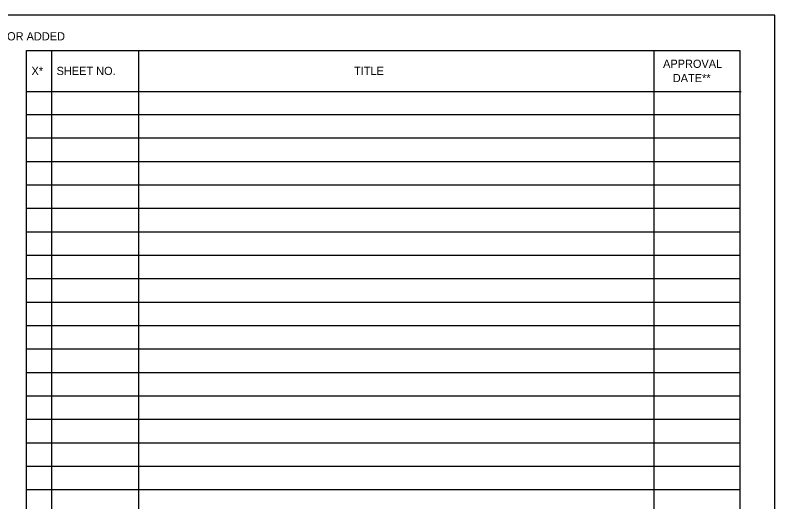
# Model space of a CAD drawing. Extents: x 0 to 5.28, y 0 to 1.73.
# Drawn here: x 1.295 to 2.646, y 0.865 to 1.729 of the extents above; entities that cross this region are included whole.
import ezdxf

# ---------------------------------------------------------------- set-up
doc = ezdxf.new("R2010")
doc.units = 0
for name, color, linetype in [('CT_Border_Perimeter_Shape', 7, 'Continuous'), ('CT_Dimensions', 7, 'Continuous'), ('CT_List_of _Standards', 7, 'Continuous')]:
    doc.layers.add(name, color=color, linetype=linetype)

msp = doc.modelspace()

# ---------------------------------------------------------------- linework, layer by layer
at = {"layer": 'CT_Border_Perimeter_Shape'}
msp.add_lwpolyline([(0, 0), (2.6458, 0), (2.6458, 1.7292), (0, 1.7292)], close=True, dxfattribs=at)
at = {"layer": 'CT_Dimensions'}
msp.add_lwpolyline([(1.3146, 1.6667), (2.5834, 1.6667), (2.5834, 0.2187), (1.3146, 0.2187)], close=True, dxfattribs=at)
msp.add_lwpolyline([(1.3146, 1.6667), (2.5834, 1.6667), (2.5834, 0.2187), (1.3146, 0.2187)], close=True, dxfattribs=at)
at = {"layer": 'CT_List_of _Standards'}
for p, q in [((1.3592, 1.6667), (1.3592, 0.2187)), ((1.5138, 1.6667), (1.5138, 0.2187)), ((2.4305, 1.6667), (2.4305, 0.2187)), ((1.3146, 1.5937), (2.5859, 1.5937)), ((1.3542, 1.5937), (2.5833, 1.5937)), ((1.3146, 1.5528), (2.5834, 1.5528)), ((1.3146, 1.5528), (2.5834, 1.5528)), ((1.3146, 1.5112), (2.5834, 1.5112)), ((1.3146, 1.5112), (2.5834, 1.5112)), ((1.3146, 1.4695), (2.5834, 1.4695)), ((1.3146, 1.4695), (2.5834, 1.4695)), ((1.3146, 1.4278), (2.5834, 1.4278)), ((1.3146, 1.4278), (2.5834, 1.4278)), ((1.3146, 1.3862), (2.5834, 1.3862)), ((1.3146, 1.3862), (2.5834, 1.3862)), ((1.3146, 1.3445), (2.5834, 1.3445)), ((1.3146, 1.3445), (2.5834, 1.3445)), ((1.3146, 1.3028), (2.5834, 1.3028)), ((1.3146, 1.3028), (2.5834, 1.3028)), ((1.3146, 1.2612), (2.5834, 1.2612)), ((1.3146, 1.2612), (2.5834, 1.2612)), ((1.3146, 1.2195), (2.5834, 1.2195)), ((1.3146, 1.2195), (2.5834, 1.2195)), ((1.3146, 1.1778), (2.5834, 1.1778)), ((1.3146, 1.1778), (2.5834, 1.1778)), ((1.3146, 1.1362), (2.5834, 1.1362)), ((1.3146, 1.1362), (2.5834, 1.1362)), ((1.3146, 1.0945), (2.5834, 1.0945)), ((1.3146, 1.0945), (2.5834, 1.0945)), ((1.3146, 1.0528), (2.5834, 1.0528)), ((1.3146, 1.0528), (2.5834, 1.0528)), ((1.3146, 1.0112), (2.5834, 1.0112)), ((1.3146, 1.0112), (2.5834, 1.0112)), ((1.3146, 0.9695), (2.5834, 0.9695)), ((1.3146, 0.9695), (2.5834, 0.9695)), ((1.3146, 0.9278), (2.5834, 0.9278)), ((1.3146, 0.9278), (2.5834, 0.9278)), ((1.3146, 0.8862), (2.5834, 0.8862))]:
    msp.add_line(p, q, dxfattribs=at)

# ---------------------------------------------------------------- texts
at = {"layer": 'CT_Dimensions'}
msp.add_text('**REVISED OR ADDED', height=0.014583, dxfattribs=at).set_placement((1.1741, 1.6844))
at = {"layer": 'CT_List_of _Standards'}
for s, p in [('APPROVAL', (2.4471, 1.6356)), ('X*', (1.3237, 1.6229)), ('SHEET NO.', (1.3683, 1.6229)), ('TITLE', (1.8974, 1.6229)), ('DATE**', (2.4644, 1.6102))]:
    msp.add_text(s, height=0.01458, dxfattribs=at).set_placement(p)

doc.saveas('drawing.dxf')
